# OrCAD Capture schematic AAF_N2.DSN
size A
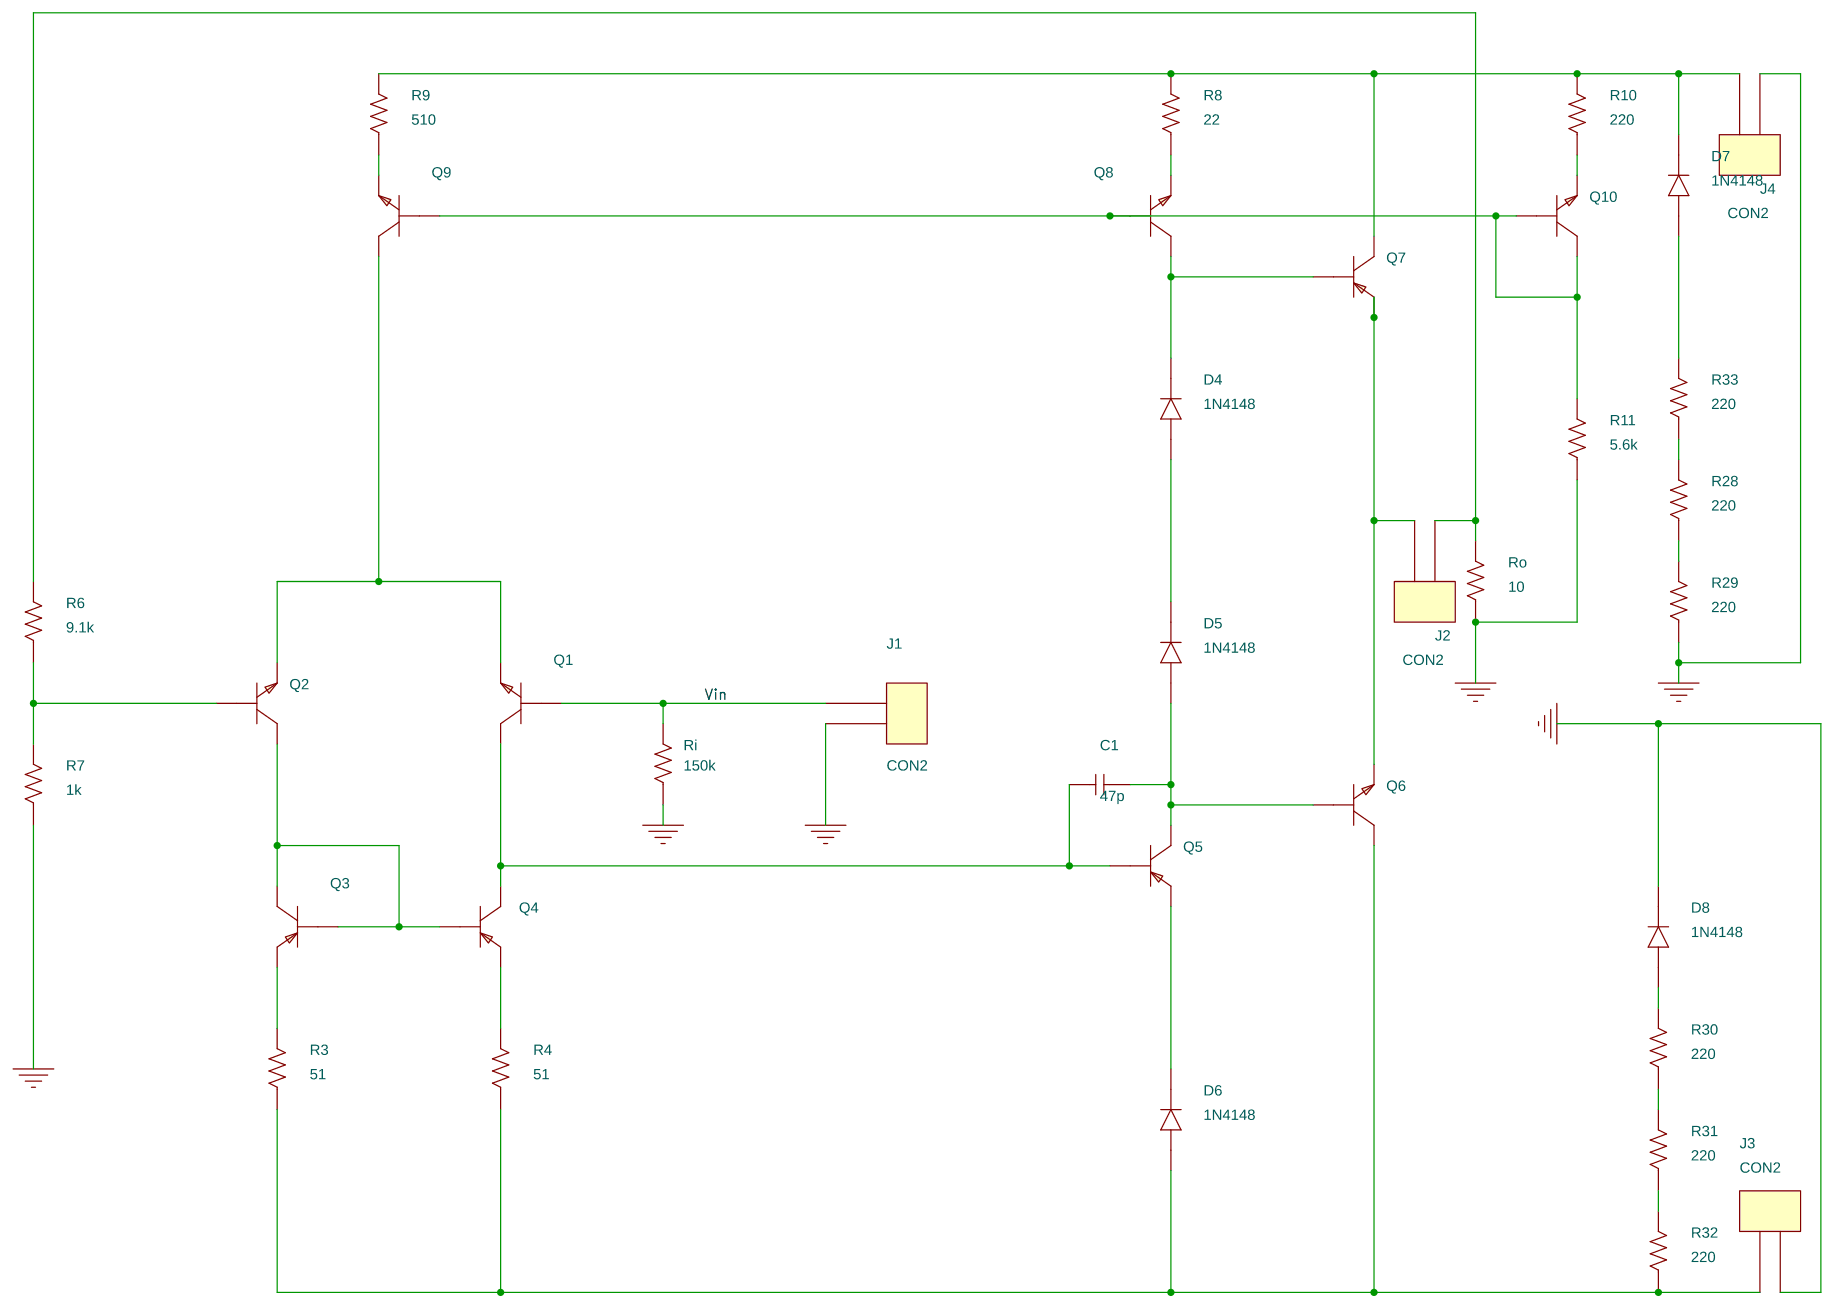
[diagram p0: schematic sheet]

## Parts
C1  47p  [SMC0805]
D4  1N4148  [SMD080512]
D5  1N4148  [SMD080512]
D6  1N4148  [SMD080512]
D7  1N4148  [SML0805]
D8  1N4148  [SML0805]
J1  CON2  [SMR2512]
J2  CON2  [SMR2512]
J3  CON2  [SMR2512]
J4  CON2  [SMR2512]
Q1  QBC846B  [TO236AA]
Q2  QBC846B  [TO236AA]
Q3  QBC807-25  [TO236AA]
Q4  QBC807-25  [TO236AA]
Q5  QBC807-25  [TO236AA]
Q6  QBC846B  [TO236AA]
Q7  QBC807-25  [TO236AA]
Q8  QBC846B  [TO236AA]
Q9  QBC846B  [TO236AA]
Q10  QBC846B  [TO236AA]
R3  51  [SMR0805]
R4  51  [SMR0805]
R6  9.1k  [SMR0805]
R7  1k  [SMR0805]
R8  22  [SMR0805]
R9  510  [SMR0805]
R10  220  [SMR0805]
R11  5.6k  [SMR0805]
R28  220  [SMR0805]
R29  220  [SMR0805]
R30  220  [SMR0805]
R31  220  [SMR0805]
R32  220  [SMR0805]
R33  220  [SMR0805]
Ri  150k  [SMR0805]
Ro  10  [SMR0805]

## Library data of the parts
C1 = C
D4-D8 = 1N4148_1
J1-J4 = CON2
Q1 Q2 Q6 Q8-Q10 = QBC846B_1
Q3-Q5 Q7 = QBC807-25_0
R3 R4 R6-R11 R28-R33 Ri Ro = R_0

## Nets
Vin: J1.1 Q1.1(B) Ri.2
0: D8.2(CAT) J1.2 J3.2 J4.2 R7.1 R11.1 R29.1 Ri.1 Ro.1
N70906: Q8.1(B) Q9.1(B) Q10.1(B) Q10.3(C) R11.2
N70950: D4.2(CAT) Q7.1(B) Q8.3(C)
N70954: D7.2(CAT) J4.1 Q7.3(C) R8.2 R9.2 R10.2
N70980: Q2.1(B) R6.1 R7.2
N71016: Q1.2(E) Q2.2(E) Q9.3(C)
N71054: Q2.3(C) Q3.1(B) Q3.3(C) Q4.1(B)
N71074: C1.1 Q1.3(C) Q4.3(C) Q5.1(B)
N71112: Q3.2(E) R3.2
N71118: Q4.2(E) R4.2
N71168: D6.1(AN) J3.1 Q6.3(C) R3.1 R4.1 R32.1
N71224: C1.2 D5.1(AN) Q5.3(C) Q6.1(B)
N71264: Q9.2(E) R9.1
N71354: D4.1(AN) D5.2(CAT)
N71386: J2.1 Q6.2(E) Q7.2(E)
N71424: J2.2 R6.2 Ro.2
N71454: Q8.2(E) R8.1
N71648: R28.1 R29.2
N71714: D8.1(AN) R30.2
N71720: R30.1 R31.2
N71774: R31.1 R32.2
N71788: R28.2 R33.1
N72108: D6.2(CAT) Q5.2(E)
N72168: Q10.2(E) R10.1
N81690: D7.1(AN) R33.2
